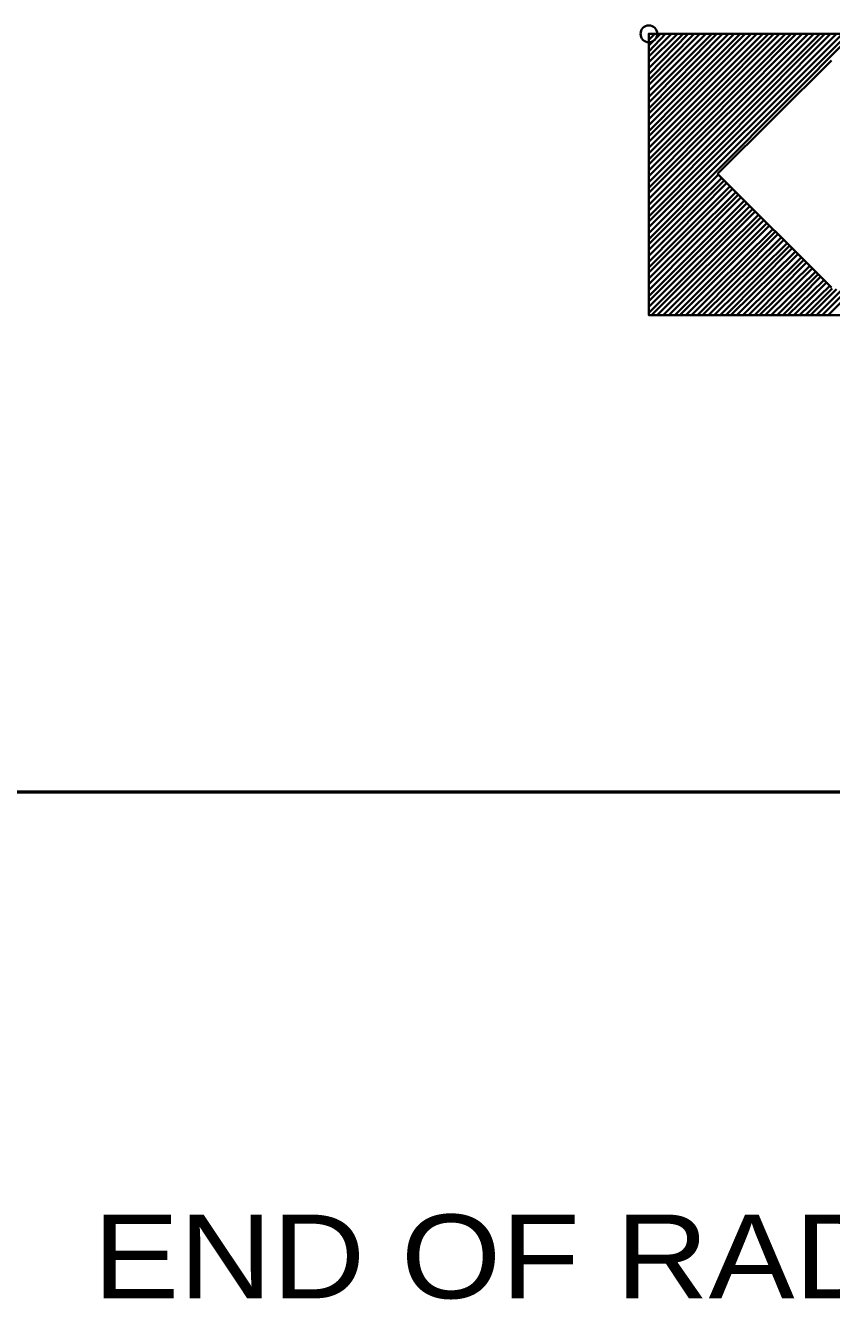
# Model space of a CAD drawing. Extents: x -133 to 547, y -328 to 112.
# Drawn here: x -57.28 to -38.04, y -30.14 to 0.28 of the extents above; entities that cross this region are included whole.
import ezdxf
from ezdxf.enums import TextEntityAlignment as Align

# ---------------------------------------------------------------- set-up
doc = ezdxf.new("R2010")
doc.units = 0
doc.header["$LTSCALE"] = 0.8
doc.header["$PDMODE"] = 32
doc.header["$PDSIZE"] = 0.4
doc.layers.add('1', color=7, linetype='Continuous', lineweight=35)

msp = doc.modelspace()

# ---------------------------------------------------------------- linework, layer by layer
at = {"layer": '1'}
for p, q in [((-42.3959, -0.0559), (-42.2559, 0.0841)), ((-42.3959, -0.1959), (-42.1159, 0.0841)), ((-42.3959, -0.3359), (-41.9959, 0.0841)), ((-42.3959, -0.4559), (-41.8559, 0.0841)), ((-42.3959, -0.5959), (-41.7159, 0.0841)), ((-42.3959, -0.7359), (-41.5759, 0.0841)), ((-42.3959, -0.8759), (-41.4559, 0.0841)), ((-42.3959, -1.0159), (-41.3159, 0.0841)), ((-42.3959, -1.1359), (-41.1759, 0.0841)), ((-42.3959, -1.2759), (-41.0359, 0.0841)), ((-42.3959, -1.4159), (-40.8959, 0.0841)), ((-42.3959, -1.5559), (-40.7759, 0.0841)), ((-42.3959, -1.6959), (-40.6359, 0.0841)), ((-42.3959, -1.8159), (-40.4959, 0.0841)), ((-42.3959, -1.9559), (-40.3559, 0.0841)), ((-42.3959, -2.0959), (-40.2159, 0.0841)), ((-42.3959, -2.2359), (-40.0959, 0.0841)), ((-42.3959, -2.3559), (-39.9559, 0.0841)), ((-42.3959, -2.4959), (-39.8159, 0.0841)), ((-42.3959, -2.6359), (-39.6759, 0.0841)), ((-42.3959, -2.7759), (-39.5359, 0.0841)), ((-42.3959, -2.9159), (-39.4159, 0.0841)), ((-42.3959, -3.0359), (-39.2759, 0.0841)), ((-42.3959, -3.1759), (-39.1359, 0.0841)), ((-42.3959, -3.3159), (-38.9959, 0.0841)), ((-42.3959, -3.4559), (-38.8759, 0.0841)), ((-42.3959, -3.5959), (-38.7359, 0.0841)), ((-42.3959, -3.7159), (-38.5959, 0.0841)), ((-42.3959, -3.8559), (-38.4559, 0.0841)), ((-42.3959, -3.9959), (-38.3159, 0.0841)), ((-42.3959, -4.1359), (-38.1959, 0.0841)), ((-42.3959, -4.2759), (-38.0559, 0.0841)), ((-42.3959, -4.3959), (-37.9159, 0.0841)), ((-42.3959, -4.5359), (-37.7759, 0.0841)), ((-42.3959, -4.6759), (-37.6359, 0.0841)), ((-42.3959, -4.8159), (-37.5159, 0.0841)), ((-42.3959, -0.0559), (-42.2559, 0.0841)), ((-42.3959, -0.1959), (-42.1159, 0.0841)), ((-42.3959, -0.3359), (-41.9959, 0.0841)), ((-42.3959, -0.4559), (-41.8559, 0.0841)), ((-42.3959, -0.5959), (-41.7159, 0.0841)), ((-42.3959, -0.7359), (-41.5759, 0.0841)), ((-42.3959, -0.8759), (-41.4559, 0.0841)), ((-42.3959, -1.0159), (-41.3159, 0.0841)), ((-42.3959, -1.1359), (-41.1759, 0.0841)), ((-42.3959, -1.2759), (-41.0359, 0.0841)), ((-42.3959, -1.4159), (-40.8959, 0.0841)), ((-42.3959, -1.5559), (-40.7759, 0.0841)), ((-42.3959, -1.6959), (-40.6359, 0.0841)), ((-42.3959, -1.8159), (-40.4959, 0.0841)), ((-42.3959, -1.9559), (-40.3559, 0.0841)), ((-42.3959, -2.0959), (-40.2159, 0.0841)), ((-42.3959, -2.2359), (-40.0959, 0.0841)), ((-42.3959, -2.3559), (-39.9559, 0.0841)), ((-42.3959, -2.4959), (-39.8159, 0.0841)), ((-42.3959, -2.6359), (-39.6759, 0.0841)), ((-42.3959, -2.7759), (-39.5359, 0.0841)), ((-42.3959, -2.9159), (-39.4159, 0.0841)), ((-42.3959, -3.0359), (-39.2759, 0.0841)), ((-42.3959, -3.1759), (-39.1359, 0.0841)), ((-42.3959, -3.3159), (-38.9959, 0.0841)), ((-42.3959, -3.4559), (-38.8759, 0.0841)), ((-42.3959, -3.5959), (-38.7359, 0.0841)), ((-42.3959, -3.7159), (-38.5959, 0.0841)), ((-42.3959, -3.8559), (-38.4559, 0.0841)), ((-42.3959, -3.9959), (-38.3159, 0.0841)), ((-42.3959, -4.1359), (-38.1959, 0.0841)), ((-42.3959, -4.2759), (-38.0559, 0.0841)), ((-42.3959, -4.3959), (-37.9159, 0.0841)), ((-42.3959, -4.5359), (-37.7759, 0.0841)), ((-42.3959, -4.6759), (-37.6359, 0.0841)), ((-42.3959, -4.8159), (-37.5159, 0.0841)), ((-40.7559, -3.2559), (-38.0359, -0.5559)), ((-40.7559, -3.2559), (-38.0359, -0.5559)), ((-42.3959, -4.9359), (-40.7359, -3.2759)), ((-42.3959, -4.9359), (-40.7359, -3.2759)), ((-38.0359, -5.9759), (-40.7559, -3.2559)), ((-38.0359, -5.9759), (-40.7559, -3.2559)), ((-42.3959, -5.0759), (-40.6559, -3.3559)), ((-42.3959, -5.0759), (-40.6559, -3.3559)), ((-42.3959, -5.2159), (-40.5959, -3.4159)), ((-42.3959, -5.2159), (-40.5959, -3.4159)), ((-42.3959, -5.3559), (-40.5359, -3.4759)), ((-42.3959, -5.3559), (-40.5359, -3.4759)), ((-42.3959, -5.4959), (-40.4559, -3.5559)), ((-42.3959, -5.4959), (-40.4559, -3.5559)), ((-42.3959, -5.6159), (-40.3959, -3.6159)), ((-42.3959, -5.6159), (-40.3959, -3.6159)), ((-42.3959, -5.7559), (-40.3159, -3.6959)), ((-42.3959, -5.7559), (-40.3159, -3.6959)), ((-42.3959, -5.8959), (-40.2559, -3.7559)), ((-42.3959, -5.8959), (-40.2559, -3.7559)), ((-42.3959, -6.0359), (-40.1959, -3.8159)), ((-42.3959, -6.0359), (-40.1959, -3.8159)), ((-42.3959, -6.1759), (-40.1159, -3.8959)), ((-42.3959, -6.1759), (-40.1159, -3.8959)), ((-42.3959, -6.2959), (-40.0559, -3.9559)), ((-42.3959, -6.2959), (-40.0559, -3.9559)), ((-42.3959, -6.4359), (-39.9959, -4.0359)), ((-42.3959, -6.4359), (-39.9959, -4.0359)), ((-42.3959, -6.5759), (-39.9159, -4.0959)), ((-42.3959, -6.5759), (-39.9159, -4.0959)), ((-42.3359, -6.6359), (-39.8559, -4.1559)), ((-42.3359, -6.6359), (-39.8559, -4.1559)), ((-42.1959, -6.6359), (-39.7759, -4.2359)), ((-42.1959, -6.6359), (-39.7759, -4.2359)), ((-42.0559, -6.6359), (-39.7159, -4.2959)), ((-42.0559, -6.6359), (-39.7159, -4.2959)), ((-41.9159, -6.6359), (-39.6559, -4.3759)), ((-41.9159, -6.6359), (-39.6559, -4.3759)), ((-41.7759, -6.6359), (-39.5759, -4.4359)), ((-41.7759, -6.6359), (-39.5759, -4.4359)), ((-41.6559, -6.6359), (-39.5159, -4.4959)), ((-41.6559, -6.6359), (-39.5159, -4.4959)), ((-41.5159, -6.6359), (-39.4359, -4.5759)), ((-41.5159, -6.6359), (-39.4359, -4.5759)), ((-41.3759, -6.6359), (-39.3759, -4.6359)), ((-41.3759, -6.6359), (-39.3759, -4.6359)), ((-41.2359, -6.6359), (-39.3159, -4.6959)), ((-41.2359, -6.6359), (-39.3159, -4.6959)), ((-41.1159, -6.6359), (-39.2359, -4.7759)), ((-41.1159, -6.6359), (-39.2359, -4.7759)), ((-40.9759, -6.6359), (-39.1759, -4.8359)), ((-40.9759, -6.6359), (-39.1759, -4.8359)), ((-38.2559, -6.6359), (-36.3159, -4.6959)), ((-38.2559, -6.6359), (-36.3159, -4.6959)), ((-38.1159, -6.6359), (-36.1759, -4.6959)), ((-38.1159, -6.6359), (-36.1759, -4.6959)), ((-40.8359, -6.6359), (-39.0959, -4.9159)), ((-40.8359, -6.6359), (-39.0959, -4.9159)), ((-40.6959, -6.6359), (-39.0359, -4.9759)), ((-40.6959, -6.6359), (-39.0359, -4.9759)), ((-40.5559, -6.6359), (-38.9759, -5.0359)), ((-40.5559, -6.6359), (-38.9759, -5.0359)), ((-40.4359, -6.6359), (-38.8959, -5.1159)), ((-40.4359, -6.6359), (-38.8959, -5.1159)), ((-40.2959, -6.6359), (-38.8359, -5.1759)), ((-40.2959, -6.6359), (-38.8359, -5.1759)), ((-40.1559, -6.6359), (-38.7559, -5.2559)), ((-40.1559, -6.6359), (-38.7559, -5.2559)), ((-40.0159, -6.6359), (-38.6959, -5.3159)), ((-40.0159, -6.6359), (-38.6959, -5.3159)), ((-39.8759, -6.6359), (-38.6359, -5.3759)), ((-39.8759, -6.6359), (-38.6359, -5.3759)), ((-39.7559, -6.6359), (-38.5559, -5.4559)), ((-39.7559, -6.6359), (-38.5559, -5.4559)), ((-39.6159, -6.6359), (-38.4959, -5.5159)), ((-39.6159, -6.6359), (-38.4959, -5.5159)), ((-39.4759, -6.6359), (-38.4159, -5.5959)), ((-39.4759, -6.6359), (-38.4159, -5.5959)), ((-39.3359, -6.6359), (-38.3559, -5.6559)), ((-39.3359, -6.6359), (-38.3559, -5.6559)), ((-39.1959, -6.6359), (-38.2959, -5.7159)), ((-39.1959, -6.6359), (-38.2959, -5.7159)), ((-39.0759, -6.6359), (-38.2159, -5.7959)), ((-39.0759, -6.6359), (-38.2159, -5.7959)), ((-38.9359, -6.6359), (-38.1559, -5.8559)), ((-38.9359, -6.6359), (-38.1559, -5.8559)), ((-38.7959, -6.6359), (-38.0759, -5.9359)), ((-38.7959, -6.6359), (-38.0759, -5.9359)), ((-38.6559, -6.6359), (-38.0159, -5.9959)), ((-38.6559, -6.6359), (-38.0159, -5.9959)), ((-38.5359, -6.6359), (-37.9159, -6.0159)), ((-38.5359, -6.6359), (-37.9159, -6.0159)), ((-38.3959, -6.6359), (-37.7759, -6.0159)), ((-38.3959, -6.6359), (-37.7759, -6.0159))]:
    msp.add_line(p, q, dxfattribs=at)
at = {"layer": '1', "lineweight": 53}
msp.add_line((-87.7097, -18.0198), (-16.0081, -18.0198), dxfattribs=at)
at = {"layer": '1'}
msp.add_lwpolyline([(-42.3959, 0.0841), (-24.1559, 0.0841), (-24.1559, -6.6359), (-42.3959, -6.6359)], close=True, dxfattribs=at)
msp.add_lwpolyline([(-42.3959, 0.0841), (-24.1559, 0.0841), (-24.1559, -6.6359), (-42.3959, -6.6359)], close=True, dxfattribs=at)
msp.add_point((-42.3959, 0.0841), dxfattribs=at)

# ---------------------------------------------------------------- texts
at = {"layer": '1', "width": 1.15}
msp.add_text('END OF RADIUS', height=2, dxfattribs=at).set_placement((-43.6165, -30.1108), align=Align.CENTER)

doc.saveas('drawing.dxf')
